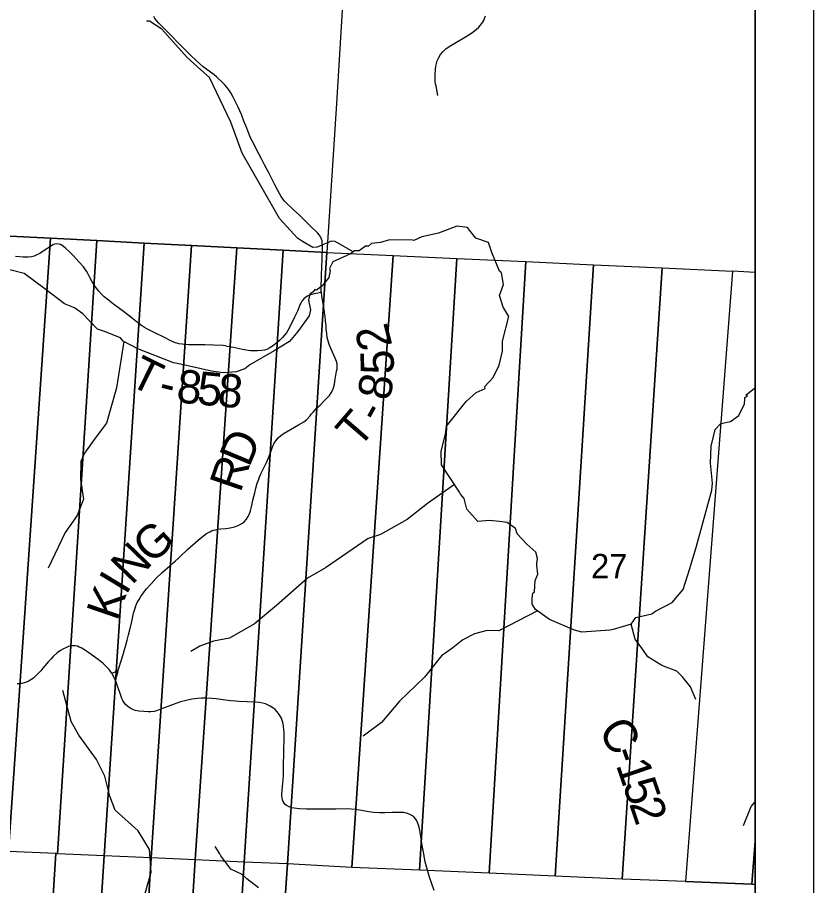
# Model space of a CAD drawing. Extents: x 0 to 34, y 0 to 22.
# Drawn here: x 7.641 to 9, y 15.074 to 16.555 of the extents above; entities that cross this region are included whole.
import ezdxf

# ---------------------------------------------------------------- set-up
doc = ezdxf.new("R2010")
doc.units = 0
for name, color, linetype in [('Default', 7, 'Continuous'), ('GM_X_County_Road', 7, 'Continuous'), ('GM_X_County_Road_Text', 7, 'Continuous'), ('GM_X_Minor_River', 7, 'Continuous'), ('GM_X_Section', 7, 'Continuous'), ('GM_X_Section_Text', 7, 'Continuous'), ('GM_X_Township_Road', 7, 'Continuous'), ('GM_X_Township_Road_Text', 7, 'Continuous'), ('SH_Cut_Line', 7, 'Continuous'), ('SH_Data', 7, 'Continuous')]:
    doc.layers.add(name, color=color, linetype=linetype)

msp = doc.modelspace()

# ---------------------------------------------------------------- linework, layer by layer
at = {"layer": 'Default'}
msp.add_lwpolyline([(6.746, 14.2985), (6.7712, 14.2974), (6.976, 14.2607), (6.9586, 14.2364), (6.8584, 14.2105), (6.8604, 14.196), (6.9571, 14.149), (7.0704, 14.1528), (7.0738, 14.1658), (7.0492, 14.1735), (7.0778, 14.1886), (7.2187, 14.1579), (7.3738, 14.1), (8.9, 14.1), (8.9, 19.1797)], dxfattribs=at)
for points in [[(8.9, 15.1494), (8.9, 16.1202), (8.8614, 16.1225), (8.7811, 15.0807), (8.8945, 15.0761)], [(8.9, 15.0758), (8.9, 15.1494), (8.8945, 15.0761)], [(7.6316, 14.1), (7.6406, 14.1), (7.7063, 15.1284), (7.6256, 15.132), (7.558, 14.1033)], [(7.6406, 14.1), (7.7231, 14.1), (7.7887, 15.1248), (7.7089, 15.1283), (7.7063, 15.1284)], [(7.7231, 14.1), (7.806, 14.1), (7.8688, 15.1212), (7.7887, 15.1248)], [(7.806, 14.1), (7.88, 14.1), (7.9439, 15.1179), (7.8688, 15.1212)], [(7.88, 14.1), (7.9647, 14.1), (8.0279, 15.1141), (7.9439, 15.1179)], [(7.9647, 14.1), (8.0319, 14.1), (8.1017, 15.1109), (8.0279, 15.1141)], [(8.0319, 14.1), (8.9, 14.1), (8.9, 15.0758), (8.8945, 15.0761), (8.7811, 15.0807), (8.6731, 15.0846), (8.5585, 15.09), (8.4462, 15.0952), (8.3272, 15.1001), (8.2115, 15.1046), (8.1017, 15.1109)]]:
    msp.add_lwpolyline(points, close=True, dxfattribs=at)
at = {"layer": 'GM_X_County_Road'}
for points in [[(7.8076, 15.4249), (7.8053, 15.4302), (7.8017, 15.4362), (7.7995, 15.4394), (7.7974, 15.4424), (7.793, 15.4474), (7.787, 15.4527), (7.7783, 15.4594), (7.7666, 15.4681), (7.7568, 15.4749), (7.7496, 15.4793), (7.7463, 15.4809), (7.7432, 15.4822), (7.7394, 15.4829), (7.736, 15.4831), (7.7323, 15.4829), (7.728, 15.4819), (7.7244, 15.4804), (7.7194, 15.4781), (7.7141, 15.475), (7.7087, 15.4709), (7.7019, 15.4647), (7.6981, 15.4609), (7.6937, 15.4562), (7.684, 15.4449), (7.6805, 15.4406), (7.6764, 15.436), (7.6729, 15.4322), (7.6684, 15.4281), (7.6634, 15.4247), (7.659, 15.4223), (7.6542, 15.4204), (7.6484, 15.4189), (7.6442, 15.4183), (7.6401, 15.4183)], [(8.3519, 15.0653), (8.3441, 15.0884), (8.3394, 15.1044), (8.3369, 15.1144), (8.3339, 15.1308), (8.3317, 15.142), (8.3297, 15.1542), (8.3275, 15.168), (8.3265, 15.1733), (8.3251, 15.1784), (8.3239, 15.1815), (8.3227, 15.1841), (8.3207, 15.1871), (8.3175, 15.191), (8.3138, 15.1937), (8.3096, 15.1957), (8.3066, 15.197), (8.3028, 15.198), (8.2997, 15.1984), (8.2962, 15.1986), (8.2888, 15.1987), (8.2807, 15.1983), (8.2677, 15.1979), (8.2589, 15.198), (8.2487, 15.1988), (8.2406, 15.1998), (8.2249, 15.2028), (8.2174, 15.2037), (8.2107, 15.2043), (8.2039, 15.2046), (8.1841, 15.2042), (8.1644, 15.2043), (8.1547, 15.2045), (8.1342, 15.2045), (8.1217, 15.2048), (8.113, 15.2057), (8.1086, 15.2067), (8.1045, 15.2081), (8.1, 15.2105), (8.098, 15.212), (8.096, 15.2145), (8.0944, 15.2174), (8.0933, 15.2204), (8.0926, 15.2235), (8.092, 15.2267), (8.092, 15.2307), (8.0924, 15.2355), (8.093, 15.2431), (8.0937, 15.2486), (8.0942, 15.2545), (8.0947, 15.2625), (8.0949, 15.2755), (8.0953, 15.3039), (8.096, 15.3254), (8.0959, 15.3346), (8.0957, 15.3402), (8.0951, 15.3458), (8.0942, 15.3507), (8.0929, 15.3555), (8.0913, 15.3596), (8.0876, 15.3659), (8.0842, 15.3703), (8.0805, 15.3741), (8.0765, 15.3772), (8.0724, 15.3799), (8.0676, 15.3825), (8.0642, 15.3839), (8.059, 15.3853), (8.0539, 15.3861), (8.0453, 15.387), (8.0329, 15.3875), (8.0186, 15.3881), (8.0131, 15.3884), (8.0044, 15.3892), (7.9919, 15.3908), (7.9799, 15.3923), (7.9727, 15.393), (7.9634, 15.3935), (7.9549, 15.3936), (7.9483, 15.3932), (7.9434, 15.3926), (7.9382, 15.3918), (7.9286, 15.3897), (7.9192, 15.3872), (7.9067, 15.383), (7.884, 15.3744), (7.8779, 15.3721), (7.8739, 15.3709), (7.8687, 15.3705), (7.8639, 15.3703), (7.8563, 15.3707), (7.848, 15.3715), (7.8417, 15.3729), (7.8365, 15.3747), (7.8332, 15.3764), (7.829, 15.3792), (7.8246, 15.3837), (7.8223, 15.387), (7.8205, 15.3899), (7.819, 15.3932), (7.8153, 15.4035), (7.8118, 15.414), (7.8097, 15.4199), (7.8076, 15.4249)]]:
    msp.add_lwpolyline(points, dxfattribs=at)
at = {"layer": 'GM_X_Minor_River'}
for points in [[(8.2138, 16.1555), (8.1834, 16.1727), (8.1763, 16.1733), (8.1525, 16.1634), (8.1449, 16.1629), (8.1275, 16.1729), (8.1186, 16.1789), (8.0879, 16.2122), (8.0243, 16.3239), (8.0051, 16.3766), (7.9689, 16.4529), (7.9538, 16.4659), (7.9306, 16.4868), (7.8871, 16.5353), (7.866, 16.5488), (7.8612, 16.5487)], [(8.4268, 15.6954), (8.4077, 15.7164), (8.4035, 15.7342), (8.3971, 15.7418), (8.3956, 15.7452), (8.3649, 15.7919), (8.3641, 15.8151), (8.3717, 15.8443), (8.3732, 15.858), (8.4068, 15.8999), (8.4241, 15.9152), (8.4393, 15.9224), (8.4389, 15.9258), (8.4528, 15.9411), (8.4634, 15.962), (8.4687, 15.9859), (8.4687, 16.0027), (8.4796, 16.0449), (8.4709, 16.0593), (8.4701, 16.0612), (8.4637, 16.0806), (8.4705, 16.0996), (8.4674, 16.1193), (8.4636, 16.1224), (8.4504, 16.1543), (8.4447, 16.1714), (8.4231, 16.1789), (8.4125, 16.1922), (8.4091, 16.1971), (8.391, 16.199), (8.3593, 16.1871), (8.3313, 16.181), (8.3173, 16.1749), (8.315, 16.1752), (8.2757, 16.1759), (8.2606, 16.1713), (8.2451, 16.1694), (8.2402, 16.1648), (8.2349, 16.1648), (8.2239, 16.1572), (8.216, 16.1572), (8.2092, 16.1522), (8.1794, 16.1384), (8.1733, 16.127), (8.1745, 16.1229), (8.1722, 16.1118), (8.1609, 16.0974), (8.1514, 16.0897), (8.1484, 16.0909), (8.1458, 16.0871), (8.1401, 16.0829), (8.1375, 16.0726), (8.1412, 16.0563), (8.139, 16.0464), (8.1194, 16.0194), (8.105, 16.0022), (8.0793, 15.9866), (8.0374, 15.9625), (8.0291, 15.9557)], [(8.0291, 15.9557), (8.0143, 15.9507), (7.9928, 15.9491), (7.972, 15.9518), (7.9138, 15.9649), (7.9073, 15.9657), (7.8461, 15.9898), (7.8211, 16.0031), (7.8169, 16.0088), (7.7893, 16.0194), (7.7776, 16.0231), (7.7523, 16.0497), (7.7383, 16.0595), (7.7213, 16.0667), (7.6876, 16.0921), (7.652, 16.1186), (7.6233, 16.1258)], [(7.8224, 16.0024), (7.8096, 15.9234), (7.793, 15.8628), (7.7737, 15.8376), (7.7552, 15.8116), (7.7487, 15.7974), (7.7485, 15.7666), (7.7535, 15.7334), (7.7425, 15.7053), (7.7223, 15.6763), (7.6933, 15.6154)], [(8.7998, 15.6533), (8.8261, 15.7488), (8.8276, 15.7606), (8.8242, 15.7948), (8.8253, 15.8237), (8.8294, 15.8424), (8.8321, 15.8522), (8.8415, 15.8625), (8.8582, 15.866), (8.8725, 15.8763), (8.8819, 15.8957), (8.8823, 15.904), (8.8823, 15.9067), (8.8868, 15.909), (8.8842, 15.9109), (8.8989, 15.9227), (8.9, 15.9233)], [(8.3869, 15.7583), (8.3407, 15.7257), (8.3059, 15.6987), (8.2605, 15.6732), (8.2395, 15.6663), (8.1669, 15.6162), (8.1357, 15.5982), (8.0829, 15.5517), (8.0457, 15.5206), (8.003, 15.4958), (7.9752, 15.4909), (7.9523, 15.4826), (7.9365, 15.4732)], [(8.6887, 15.5197), (8.6577, 15.5106), (8.6521, 15.5098), (8.6044, 15.5063), (8.592, 15.5096), (8.5489, 15.5278), (8.525, 15.5452), (8.5197, 15.5539), (8.5197, 15.5646), (8.5205, 15.573), (8.5235, 15.5752), (8.5246, 15.5946), (8.5291, 15.6053), (8.5272, 15.6201), (8.5272, 15.6235), (8.5287, 15.6323), (8.5257, 15.6429), (8.5102, 15.6565), (8.4939, 15.6744), (8.4909, 15.6835), (8.4769, 15.6937), (8.4636, 15.6952), (8.4463, 15.6971), (8.4268, 15.6954)], [(8.7989, 15.3915), (8.7898, 15.4128), (8.7754, 15.4306), (8.7663, 15.4397), (8.7436, 15.4484), (8.7394, 15.4503), (8.7171, 15.4643), (8.7069, 15.4791), (8.6952, 15.4943), (8.6887, 15.5197), (8.6963, 15.5315), (8.7235, 15.5377), (8.7299, 15.5419), (8.7583, 15.5568), (8.7703, 15.5712), (8.7771, 15.5789), (8.7888, 15.615), (8.7998, 15.6533)], [(8.5284, 15.5427), (8.4626, 15.5088), (8.4426, 15.5094), (8.4209, 15.5037), (8.4013, 15.4933), (8.3839, 15.4794), (8.3646, 15.466), (8.3359, 15.4293), (8.293, 15.3885), (8.2621, 15.3523), (8.2311, 15.3286)], [(7.6922, 14.8173), (7.7125, 14.8558), (7.7868, 14.9502), (7.8334, 15.0027), (7.8539, 15.0426), (7.8692, 15.0968), (7.8662, 15.1356), (7.8471, 15.1674), (7.8077, 15.2028), (7.7982, 15.2263), (7.7898, 15.2607), (7.7756, 15.2893), (7.7455, 15.3305), (7.7326, 15.354), (7.7183, 15.4065)], [(8.8802, 15.1766), (8.8933, 15.2089), (8.9, 15.2169)], [(8.0522, 15.0698), (8.0325, 15.0854), (8.0242, 15.093), (8.0049, 15.102), (7.9879, 15.1244), (7.986, 15.1278), (7.9784, 15.1404)]]:
    msp.add_lwpolyline(points, dxfattribs=at)
at = {"layer": 'GM_X_Section'}
for points in [[(8.2333, 17.168), (8.2168, 16.9137), (8.2009, 16.6614), (8.1857, 16.4083), (8.1692, 16.1543), (8.0945, 16.1581), (8.0152, 16.1622), (7.938, 16.1663), (7.8569, 16.1703), (7.7763, 16.1745), (7.6973, 16.1784), (7.6162, 16.1827), (7.5294, 16.1877), (7.4574, 16.1913), (7.3717, 16.1957), (7.289, 16.1999), (7.2077, 16.2041), (7.123, 16.2082), (7.1862, 17.219)], [(7.6973, 16.1784), (7.6256, 15.132), (7.5463, 15.1356), (7.6162, 16.1827)], [(7.7763, 16.1745), (7.7089, 15.1283), (7.7063, 15.1284), (7.6256, 15.132), (7.6973, 16.1784)], [(7.8569, 16.1703), (7.7887, 15.1248), (7.7089, 15.1283), (7.7763, 16.1745)], [(7.938, 16.1663), (7.8688, 15.1212), (7.7887, 15.1248), (7.8569, 16.1703)], [(8.0152, 16.1622), (7.9439, 15.1179), (7.8688, 15.1212), (7.938, 16.1663)], [(8.0945, 16.1581), (8.0279, 15.1141), (7.9439, 15.1179), (8.0152, 16.1622)], [(8.1692, 16.1543), (8.1017, 15.1109), (8.0279, 15.1141), (8.0945, 16.1581)], [(8.2824, 16.1491), (8.2115, 15.1046), (8.1017, 15.1109), (8.1692, 16.1543)], [(8.3908, 16.1441), (8.3272, 15.1001), (8.2115, 15.1046), (8.2824, 16.1491)], [(8.5085, 16.1387), (8.4462, 15.0952), (8.3272, 15.1001), (8.3908, 16.1441)], [(8.6239, 16.1334), (8.5585, 15.09), (8.4462, 15.0952), (8.5085, 16.1387)], [(8.7416, 16.128), (8.6731, 15.0846), (8.5585, 15.09), (8.6239, 16.1334)], [(8.8614, 16.1225), (8.7811, 15.0807), (8.6731, 15.0846), (8.7416, 16.128)]]:
    msp.add_lwpolyline(points, close=True, dxfattribs=at)
at = {"layer": 'GM_X_Township_Road'}
for points in [[(7.8076, 15.4249), (7.8086, 15.4265), (7.8093, 15.4281), (7.8099, 15.4299), (7.8119, 15.4376), (7.8129, 15.4412), (7.819, 15.4606), (7.8258, 15.4843), (7.8282, 15.4924), (7.8306, 15.5019), (7.8326, 15.5103), (7.8358, 15.5244), (7.837, 15.5301), (7.8391, 15.5388), (7.8406, 15.5438), (7.8431, 15.5513), (7.8454, 15.5567), (7.8483, 15.5621), (7.8513, 15.5672), (7.8552, 15.5726), (7.8613, 15.5804), (7.8688, 15.5888), (7.8777, 15.5982), (7.8878, 15.608), (7.9007, 15.6194), (7.9066, 15.6248), (7.9098, 15.6277), (7.9149, 15.6323), (7.9177, 15.6348), (7.9319, 15.6477), (7.9495, 15.6634), (7.9581, 15.6706), (7.9637, 15.6745), (7.9691, 15.6776), (7.9721, 15.679), (7.9754, 15.6801), (7.9789, 15.6811), (7.9826, 15.6818), (7.988, 15.6824), (7.9963, 15.683), (8.004, 15.6844), (8.0112, 15.6862), (8.0173, 15.6882), (8.0216, 15.6905), (8.025, 15.6926), (8.0277, 15.6947), (8.0316, 15.6993), (8.0347, 15.7039), (8.0363, 15.7072), (8.0384, 15.7132), (8.0397, 15.7177), (8.0414, 15.7252), (8.0428, 15.7314), (8.0459, 15.744), (8.048, 15.7521), (8.0502, 15.7606), (8.052, 15.7657), (8.0535, 15.7694), (8.0571, 15.7776), (8.0661, 15.7958), (8.0678, 15.7998), (8.0695, 15.8037), (8.0727, 15.8124), (8.0757, 15.8211), (8.0785, 15.8278), (8.08, 15.8307), (8.0817, 15.8331), (8.0856, 15.8377), (8.0902, 15.8418), (8.0962, 15.846), (8.1068, 15.8522), (8.1207, 15.8599), (8.1294, 15.8655), (8.1348, 15.8695), (8.1403, 15.8753), (8.1424, 15.8781), (8.1454, 15.882), (8.1494, 15.8865), (8.1519, 15.8892), (8.1574, 15.8939), (8.1644, 15.9008), (8.1679, 15.9043), (8.1732, 15.9103), (8.1764, 15.9149), (8.1784, 15.9187), (8.1803, 15.9232), (8.182, 15.9298), (8.1834, 15.9383), (8.185, 15.9484), (8.1857, 15.9517), (8.1864, 15.9554), (8.1867, 15.9591), (8.1863, 15.964), (8.1853, 15.9682), (8.1829, 15.9739), (8.1761, 15.9892), (8.1728, 15.9973), (8.1705, 16.005), (8.1695, 16.009), (8.1687, 16.0161), (8.168, 16.0234), (8.1677, 16.0297), (8.1669, 16.037), (8.1659, 16.0451), (8.165, 16.0521), (8.1643, 16.0569), (8.162, 16.07), (8.1609, 16.0765), (8.1603, 16.081), (8.1598, 16.0847), (8.1597, 16.0863), (8.1595, 16.0883), (8.1594, 16.0922), (8.16, 16.1157), (8.1609, 16.1427), (8.1615, 16.1657), (8.1612, 16.1709), (8.1607, 16.1741), (8.1599, 16.1772), (8.1586, 16.1802), (8.1571, 16.1824), (8.1558, 16.1844), (8.1534, 16.1873), (8.1495, 16.191), (8.1444, 16.1958), (8.1374, 16.2028), (8.1318, 16.2084), (8.1267, 16.2134), (8.1216, 16.2183), (8.1121, 16.2273), (8.0967, 16.242), (8.0936, 16.2456), (8.0907, 16.2498), (8.0885, 16.254), (8.0846, 16.2613), (8.0801, 16.2696), (8.0697, 16.2899), (8.0626, 16.3037), (8.058, 16.3131), (8.0529, 16.3227), (8.0484, 16.3312), (8.0435, 16.3405), (8.0393, 16.3486), (8.0357, 16.3571), (8.0322, 16.3661), (8.0274, 16.3785), (8.023, 16.3895), (8.0175, 16.4022), (8.0127, 16.4123), (8.009, 16.4191), (8.0048, 16.4265), (8.0014, 16.4316), (7.9983, 16.4361), (7.9944, 16.4407), (7.9891, 16.446), (7.9833, 16.4514), (7.9808, 16.4538), (7.9764, 16.4574), (7.9682, 16.4635), (7.958, 16.4713), (7.9465, 16.4812), (7.936, 16.491), (7.9249, 16.5021), (7.9136, 16.5137), (7.9047, 16.5226), (7.8961, 16.5316), (7.8922, 16.5355), (7.8887, 16.539), (7.886, 16.5416), (7.882, 16.5454), (7.878, 16.55), (7.8755, 16.5535), (7.8737, 16.5568)], [(8.3584, 16.4224), (8.3553, 16.4386), (8.3546, 16.4421), (8.3541, 16.4453), (8.3539, 16.4483), (8.3538, 16.4527), (8.354, 16.4576), (8.3545, 16.4677), (8.3557, 16.4744), (8.3575, 16.481), (8.3599, 16.4867), (8.363, 16.4921), (8.3669, 16.4969), (8.3719, 16.5015), (8.3775, 16.5055), (8.3904, 16.513), (8.4059, 16.5221), (8.4157, 16.5287), (8.4192, 16.5312), (8.424, 16.5348), (8.4285, 16.539), (8.4331, 16.5443), (8.435, 16.5475), (8.4367, 16.5503), (8.4382, 16.5535), (8.44, 16.5579)], [(8.1597, 16.0863), (8.1583, 16.086), (8.1537, 16.085), (8.1481, 16.0838), (8.1434, 16.0827), (8.1394, 16.0815), (8.136, 16.0799), (8.1328, 16.0779), (8.1295, 16.075), (8.1263, 16.071), (8.1244, 16.0678), (8.1231, 16.0651), (8.121, 16.06), (8.1188, 16.0542), (8.1168, 16.0497), (8.114, 16.0438), (8.1061, 16.0283), (8.1024, 16.0209), (8.1, 16.0169), (8.0969, 16.0129), (8.0935, 16.009), (8.0884, 16.0043), (8.0834, 15.9999), (8.0764, 15.9946), (8.0706, 15.9909), (8.0663, 15.9889), (8.0627, 15.9877), (8.0579, 15.9867), (8.0506, 15.9862), (8.045, 15.9862), (8.0388, 15.9866), (8.0344, 15.987), (8.0249, 15.9886), (8.0094, 15.9921), (7.9988, 15.994), (7.9957, 15.9947), (7.9918, 15.9953), (7.9754, 15.9961), (7.9607, 15.9967), (7.9442, 15.9966), (7.9328, 15.9965), (7.9219, 15.9975), (7.9163, 15.9985), (7.9091, 16.0004), (7.9024, 16.0037), (7.8917, 16.009), (7.8741, 16.0177), (7.8652, 16.0221), (7.8615, 16.0239), (7.8575, 16.0263), (7.8525, 16.0295), (7.8456, 16.0347), (7.8374, 16.0418), (7.8217, 16.0535), (7.8047, 16.0661), (7.796, 16.0726), (7.7889, 16.0783), (7.7844, 16.0829), (7.7797, 16.0882), (7.7735, 16.0964), (7.7678, 16.1053), (7.7643, 16.1117), (7.7611, 16.1184), (7.7585, 16.1225), (7.7533, 16.1297), (7.7458, 16.1384), (7.7365, 16.1483), (7.7292, 16.156), (7.7232, 16.1613), (7.7187, 16.1649), (7.7141, 16.1676), (7.7107, 16.1684), (7.7068, 16.1688), (7.7039, 16.1683), (7.7011, 16.1674), (7.6972, 16.1647), (7.6862, 16.1574), (7.6787, 16.1524), (7.6737, 16.15), (7.6692, 16.1479), (7.6647, 16.1468), (7.6588, 16.1462), (7.6505, 16.1463), (7.6377, 16.1471)], [(7.8017, 15.4362), (7.8048, 15.4375), (7.8078, 15.4388), (7.8097, 15.4395), (7.8129, 15.4412)]]:
    msp.add_lwpolyline(points, dxfattribs=at)
at = {"layer": 'SH_Cut_Line'}
msp.add_lwpolyline([(6.746, 14.2985), (6.7712, 14.2974), (6.976, 14.2607), (6.9586, 14.2364), (6.8584, 14.2105), (6.8604, 14.196), (6.9571, 14.149), (7.0704, 14.1528), (7.0738, 14.1658), (7.0492, 14.1735), (7.0778, 14.1886), (7.2187, 14.1579), (7.3738, 14.1), (8.9, 14.1), (8.9, 20.9)], dxfattribs=at)
at = {"layer": 'SH_Data'}
for p, q in [((9, 21), (9, 14)), ((8.9, 20.9), (8.9, 14.1))]:
    msp.add_line(p, q, dxfattribs=at)

# ---------------------------------------------------------------- texts
at = {"layer": 'GM_X_County_Road_Text'}
for s, rotation, p in [('C', 302.5165, (8.6308, 15.3381)), ('-', 289.1348, (8.6544, 15.3019)), ('1', 288.8052, (8.662, 15.28)), ('5', 288.7608, (8.6733, 15.2468)), ('2', 288.7435, (8.6845, 15.2137))]:
    msp.add_text(s, height=0.0568, rotation=rotation, dxfattribs=at).set_placement(p)
at = {"layer": 'GM_X_Section_Text'}
msp.add_text('27', height=0.04186, rotation=0, dxfattribs=at).set_placement((8.6199, 15.5981))
at = {"layer": 'GM_X_Township_Road_Text'}
for s, rotation, p in [('2', 104.1915, (8.2811, 15.9957)), ('T', 333.732, (7.8287, 15.9295)), ('5', 91.23, (8.2837, 15.9468)), ('8', 354.3683, (7.9108, 15.8988)), ('5', 354.5678, (7.9458, 15.8953)), ('8', 354.7543, (7.9809, 15.892)), ('8', 79.4972, (8.2763, 15.8998)), ('-', 345.7027, (7.879, 15.9062)), ('T', 49.1872, (8.2232, 15.818)), ('-', 61.175, (8.2584, 15.8608)), ('D', 67.2914, (8.0362, 15.7861)), ('R', 70.9763, (8.0213, 15.7429)), ('G', 42.6863, (7.8701, 15.6207)), ('N', 46.0162, (7.836, 15.5854)), ('I', 58.8481, (7.826, 15.5681)), ('K', 70.9988, (7.811, 15.5237))]:
    msp.add_text(s, height=0.0568, rotation=rotation, dxfattribs=at).set_placement(p)

doc.saveas('drawing.dxf')
